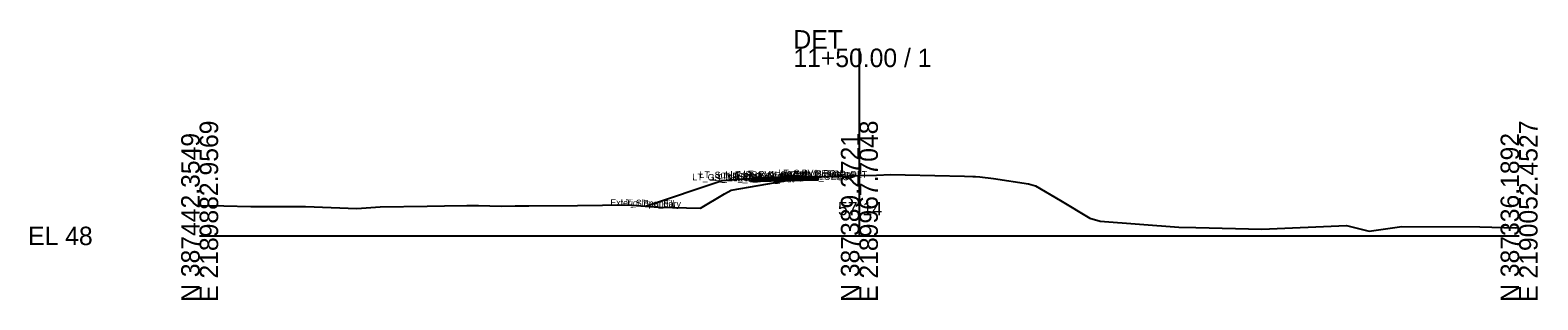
# Model space of a CAD drawing. Extents: x -26 to 1203, y -10 to 9543.
# Drawn here: x -25.7 to 202.8, y 1490.3 to 1531.2 of the extents above; entities that cross this region are included whole.
import ezdxf

# ---------------------------------------------------------------- set-up
doc = ezdxf.new("R2010")
doc.units = 0
for name, color, linetype in [('Default', 7, 'Continuous'), ('Exist Cross Section Cell', 7, 'Continuous'), ('Exist XS Center Line Elevation Label', 7, 'Continuous'), ('Exist XS Ground Line', 7, 'Continuous'), ('Prop CMT Pvmt Course 1', 7, 'Continuous'), ('Prop CMT Pvmt Course 2', 7, 'Continuous'), ('Prop CMT Pvmt Surface', 7, 'Continuous'), ('Prop CMT Pvmt Surface Shoulder', 7, 'Continuous'), ('Prop CMT Shld Paved Course 1', 7, 'Continuous'), ('Prop CMT Shld Paved Course 2', 7, 'Continuous'), ('Prop CMT Slope Grass', 7, 'Continuous'), ('Prop CMT Subgrade Earthwork', 7, 'Continuous'), ('Scratch_Level_0', 7, 'Continuous')]:
    doc.layers.add(name, color=color, linetype=linetype)

msp = doc.modelspace()

# ---------------------------------------------------------------- linework, layer by layer
at = {"layer": 'Exist Cross Section Cell'}
for p, q in [((100, 1500), (100, 1528.39)), ((0, 1500), (100, 1500)), ((100, 1500), (200, 1500))]:
    msp.add_line(p, q, dxfattribs=at)
at = {"layer": 'Exist XS Ground Line'}
for p, q in [((80.57, 1506.94), (88.76, 1508.33)), ((88.76, 1508.33), (90.36, 1508.6)), ((90.36, 1508.6), (92.14, 1508.89)), ((92.14, 1508.89), (93.76, 1508.94)), ((93.76, 1508.94), (100, 1509.14)), ((100, 1509.14), (102.6, 1509.22)), ((102.6, 1509.22), (104.76, 1509.29)), ((104.76, 1509.29), (106.94, 1509.26)), ((106.94, 1509.26), (115.92, 1509.08)), ((115.92, 1509.08), (117.22, 1509.03)), ((117.22, 1509.03), (117.58, 1509.01)), ((117.58, 1509.01), (118.25, 1508.97)), ((118.25, 1508.97), (120.33, 1508.71)), ((120.33, 1508.71), (125.65, 1507.91)), ((75.9, 1504.19), (79.54, 1506.39)), ((79.54, 1506.39), (80.57, 1506.94)), ((125.65, 1507.91), (126.72, 1507.6)), ((126.72, 1507.6), (130.48, 1505.35)), ((0, 1504.6), (3.68, 1504.58)), ((3.68, 1504.58), (7.74, 1504.47)), ((7.74, 1504.47), (15.4, 1504.47)), ((15.4, 1504.47), (16.03, 1504.44)), ((16.03, 1504.44), (23.83, 1504.16)), ((23.83, 1504.16), (27.37, 1504.4)), ((27.37, 1504.4), (34.5, 1504.49)), ((34.5, 1504.49), (37.12, 1504.54)), ((37.12, 1504.54), (40.51, 1504.61)), ((40.51, 1504.61), (42.28, 1504.59)), ((42.28, 1504.59), (45.71, 1504.51)), ((45.71, 1504.51), (47.83, 1504.57)), ((47.83, 1504.57), (49.88, 1504.57)), ((49.88, 1504.57), (57.29, 1504.61)), ((57.29, 1504.61), (64.83, 1504.72)), ((64.83, 1504.72), (69.54, 1504.36)), ((69.54, 1504.36), (75.9, 1504.19)), ((130.48, 1505.35), (134.92, 1502.67)), ((134.92, 1502.67), (136.49, 1502.26)), ((136.49, 1502.26), (148.44, 1501.32)), ((161.01, 1501.02), (173.85, 1501.6)), ((173.85, 1501.6), (177.27, 1500.72)), ((148.44, 1501.32), (151, 1501.27)), ((151, 1501.27), (161.01, 1501.02)), ((177.27, 1500.72), (182.23, 1501.44)), ((182.23, 1501.44), (194.03, 1501.36)), ((194.03, 1501.36), (199.52, 1501.21)), ((199.52, 1501.21), (200, 1501.27))]:
    msp.add_line(p, q, dxfattribs=at)
at = {"layer": 'Prop CMT Pvmt Course 1'}
for points in [[(93.77, 1509.01), (86.52, 1508.83)], [(86.52, 1508.83), (86.52, 1508.58)], [(86.52, 1508.58), (93.77, 1508.76)], [(93.77, 1508.76), (93.77, 1509.01)]]:
    msp.add_lwpolyline(points, dxfattribs=at)
at = {"layer": 'Prop CMT Pvmt Course 2'}
for points in [[(93.77, 1508.76), (86.52, 1508.58)], [(86.52, 1508.58), (86.52, 1508.33)], [(86.52, 1508.33), (93.77, 1508.51)], [(93.77, 1508.51), (93.77, 1508.76)]]:
    msp.add_lwpolyline(points, dxfattribs=at)
at = {"layer": 'Prop CMT Pvmt Surface'}
msp.add_lwpolyline([(93.77, 1509.01), (86.52, 1508.83)], dxfattribs=at)
at = {"layer": 'Prop CMT Pvmt Surface Shoulder'}
msp.add_lwpolyline([(86.52, 1508.83), (84.52, 1508.77)], dxfattribs=at)
at = {"layer": 'Prop CMT Shld Paved Course 1'}
for points in [[(86.52, 1508.83), (84.52, 1508.77), (84.27, 1508.52)], [(84.27, 1508.52), (86.52, 1508.58)], [(86.52, 1508.58), (86.52, 1508.83)]]:
    msp.add_lwpolyline(points, dxfattribs=at)
at = {"layer": 'Prop CMT Shld Paved Course 2'}
for points in [[(86.52, 1508.58), (84.27, 1508.52), (83.77, 1508.51), (83.51, 1508.25)], [(83.51, 1508.25), (86.52, 1508.33)], [(86.52, 1508.33), (86.52, 1508.58)]]:
    msp.add_lwpolyline(points, dxfattribs=at)
at = {"layer": 'Prop CMT Slope Grass'}
for points in [[(79.22, 1508.35), (67.57, 1504.46)], [(84.52, 1508.77), (79.22, 1508.35)]]:
    msp.add_lwpolyline(points, dxfattribs=at)
at = {"layer": 'Prop CMT Subgrade Earthwork'}
for points in [[(83.51, 1508.25), (83.1, 1508.66)], [(86.52, 1508.33), (83.51, 1508.25)], [(86.52, 1508.33), (93.77, 1508.51), (93.77, 1508.94)]]:
    msp.add_lwpolyline(points, dxfattribs=at)

# ---------------------------------------------------------------- texts
at = {"layer": 'Default'}
msp.add_text('-', height=0.0001, dxfattribs=at).set_placement((0, 1500))
at = {"layer": 'Exist Cross Section Cell'}
for s, p in [('DET', (90, 1528.39)), ('11+50.00 / 1', (90, 1525.59)), ('EL 48', (-26, 1498.6))]:
    msp.add_text(s, height=2.8, dxfattribs=at).set_placement(p)
for s, p in [('N 387442.3549', (0, 1490)), ('E 2189882.9569', (2.8, 1490)), ('N 387389.2721', (100, 1490)), ('E 2189967.7048', (102.8, 1490)), ('N 387336.1892', (200, 1490)), ('E 2190052.4527', (202.8, 1490))]:
    msp.add_text(s, height=2.8, rotation=90, dxfattribs=at).set_placement(p)
at = {"layer": 'Exist XS Center Line Elevation Label'}
msp.add_text('57.14', height=2, dxfattribs=at).set_placement((96.75, 1503.14))
at = {"layer": 'Scratch_Level_0'}
for s, p in [('LT_GS_OS_CTL', (74.69, 1508.44)), ('LT_Sub_Trench_Out_DLT', (75.75, 1508.8)), ('LT_Sub_Trench_Out', (77.62, 1508.36)), ('LT_PS2_Shelf_Out', (78.43, 1508.61)), ('LT_PS2_OEOP', (80.06, 1508.6)), ('LT_PS1_OEOP', (80.43, 1508.85)), ('LT_PV2_OEOT', (82.27, 1508.66)), ('LT_Sub_OEOT', (82.29, 1508.41)), ('LT_PV1_OEOT', (82.39, 1508.91)), ('LT_Sub_OEEOP_DLT', (87.73, 1509.07)), ('Exterior Boundary', (88.44, 1509.06)), ('LT_PV2_OEEOP', (89.16, 1508.85)), ('LT_Sub_OEEOP', (89.18, 1508.6)), ('PV1_PGL', (91.24, 1509.06)), ('Exterior Boundary', (62.24, 1504.57)), ('LT_Slope_Fill', (63.81, 1504.54))]:
    msp.add_text(s, height=1, rotation=358.8836, dxfattribs=at).set_placement(p)

doc.saveas('drawing.dxf')
